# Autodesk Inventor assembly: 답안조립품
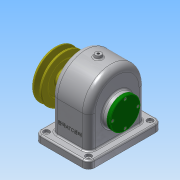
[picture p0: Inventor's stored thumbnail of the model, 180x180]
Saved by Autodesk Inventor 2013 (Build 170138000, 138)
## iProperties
Created: 2016-10
Part Number: 답안조립품
Document SubType Name: Assembly
Designer: Administrator
Author: Administrator
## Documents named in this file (15)
- C:\Users\Administrator\Desktop\461008V1027\답안조립품.iam
- C:\Users\Administrator\Desktop\461008V1027\본체.ipt
- C:\Users\Administrator\Desktop\461008V1027\베어링 6203.ipt
- C:\Users\Administrator\Desktop\461008V1027\뒤커버.ipt
- C:\Users\Administrator\Desktop\461008V1027\앞커버.ipt
- C:\Users\Administrator\Desktop\461008V1027\볼트 M3 x 10.ipt
- C:\Users\Administrator\Desktop\461008V1027\볼트 M3 x 8.ipt
- C:\Users\Administrator\Desktop\461008V1027\축.ipt
- C:\Users\Administrator\Desktop\461008V1027\키 - 6 x 6 x 22.ipt
- C:\Users\Administrator\Desktop\461008V1027\키 - 5 x 5 x 18.ipt
- C:\Users\Administrator\Desktop\461008V1027\스퍼기어.ipt
- C:\Users\Administrator\Desktop\461008V1027\부시.ipt
- C:\Users\Administrator\Desktop\461008V1027\오일씰 28 40 8.ipt
- C:\Users\Administrator\Desktop\461008V1027\V-벨트풀리.ipt
- C:\Users\Administrator\Desktop\461008V1027\멈춤나사 - M4x10.ipt
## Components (9 placed, 3 different names)
1. V-벨트풀리:1 — 각도:4
2. ISO 4762 M3 x 10:1
3. ISO 4762 M3 x 10:2
4. ISO 4762 M3 x 10:3
5. ISO 4762 M3 x 10:4
6. ISO 4762 M3 x 8:1
7. ISO 4762 M3 x 8:2
8. ISO 4762 M3 x 8:3
9. ISO 4762 M3 x 8:4
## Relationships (1: Angle 1)
- 각도:4 [Angle]: V-벨트풀리:1
